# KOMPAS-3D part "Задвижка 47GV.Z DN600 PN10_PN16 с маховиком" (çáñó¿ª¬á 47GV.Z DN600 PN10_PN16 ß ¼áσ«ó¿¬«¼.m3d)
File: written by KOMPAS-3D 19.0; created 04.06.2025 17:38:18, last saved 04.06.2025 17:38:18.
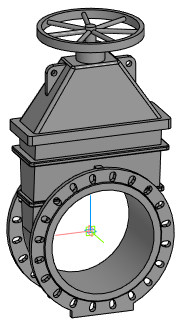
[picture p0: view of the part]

Document properties: Автор: Евгений; Полное имя файла: E:\Dendor Работа Сачек\3D для проекитирвщиков\2.1 Тип 47GV, 47GV.Z Задвижка клиновая фланцевая с обрезиненным клином\stp_Тип 47GV.Z. Задвижка DN40-DN350 с маховиком\Задвижка 47GV.Z DN600 PN10_PN16 с маховиком.m3d

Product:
- Part/product: Задвижка 47GV.Z DN600 PN10_PN16 с маховиком

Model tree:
1. Операция без истории:1  (labels: Задвижка 47GV.Z DN600 PN10_PN16 с маховиком)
